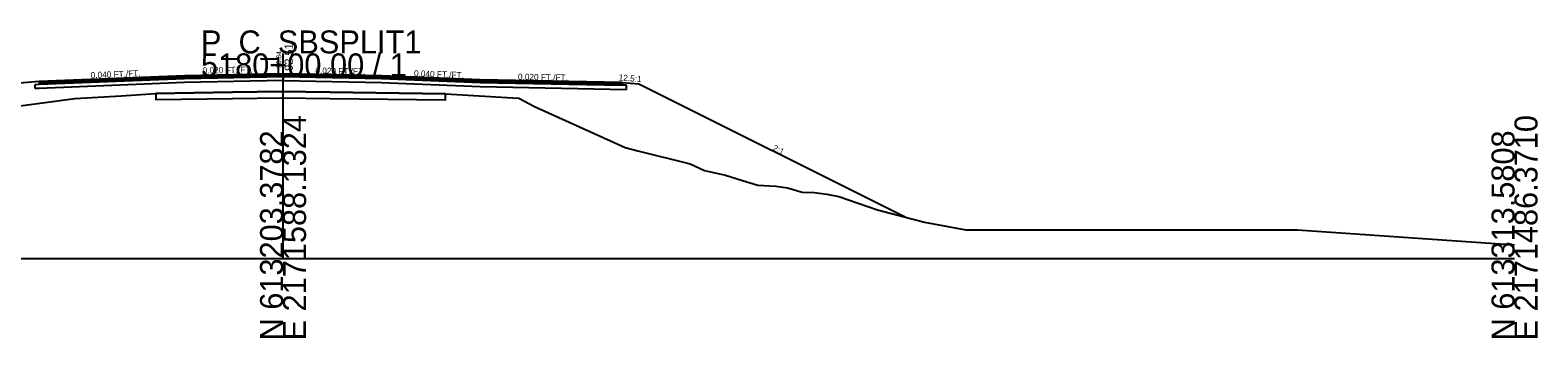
# Model space of a CAD drawing. Extents: x -26 to 1303, y -3010 to 12023.
# Drawn here: x 119.2 to 302.8, y 4490.3 to 4527.8 of the extents above; entities that cross this region are included whole.
import ezdxf

# ---------------------------------------------------------------- set-up
doc = ezdxf.new("R2010")
doc.units = 0
for name, color, linetype in [('RD_GPK_XS_Cell', 7, 'Continuous'), ('RD_XS_Base', 7, 'Continuous'), ('RD_XS_ExGround', 7, 'Continuous'), ('RD_XS_ExPaveRet', 7, 'Continuous'), ('RD_XS_Greenside', 7, 'Continuous'), ('RD_XS_Pave', 7, 'Continuous'), ('RD_XS_PaveOvlay_CP', 7, 'Continuous'), ('RD_XS_TieSlope', 7, 'Continuous'), ('RD_XS_TX_Elev_EX', 7, 'Continuous'), ('RD_XS_TX_Elev_PR', 7, 'Continuous'), ('RD_XS_TX_ShdSlope', 7, 'Continuous'), ('RD_XS_TX_Slope', 7, 'Continuous')]:
    doc.layers.add(name, color=color, linetype=linetype)

msp = doc.modelspace()

# ---------------------------------------------------------------- linework, layer by layer
at = {"layer": 'RD_GPK_XS_Cell'}
for p, q in [((150, 4500), (150, 4525)), ((0, 4500), (150, 4500)), ((150, 4500), (300, 4500))]:
    msp.add_line(p, q, dxfattribs=at)
at = {"layer": 'RD_XS_Base'}
for p, q in [((120.31, 4521.24), (138, 4521.95)), ((138, 4521.45), (120.31, 4520.74)), ((138, 4521.95), (150, 4522.19)), ((150, 4521.69), (138, 4521.45)), ((150, 4522.19), (150, 4522.35)), ((150, 4522.35), (150, 4521.69)), ((150, 4522.19), (150, 4522.19)), ((162, 4521.95), (150, 4522.19)), ((150, 4522.19), (150, 4522.19)), ((150, 4522.19), (150, 4521.69)), ((150, 4521.69), (150, 4521.69)), ((150, 4521.69), (162, 4521.45)), ((150, 4521.69), (150, 4521.69)), ((174, 4521.47), (162, 4521.95)), ((162, 4521.95), (162, 4521.95)), ((162, 4521.45), (162, 4521.45)), ((162, 4521.45), (174, 4520.97)), ((191.32, 4521.12), (174, 4521.47)), ((174, 4521.47), (174, 4521.47)), ((119.81, 4521.22), (120.31, 4521.24)), ((119.81, 4520.72), (119.81, 4521.22)), ((119.81, 4521.22), (119.81, 4521.22)), ((120.31, 4520.74), (119.81, 4520.72)), ((119.81, 4520.72), (119.81, 4520.72)), ((119.81, 4520.72), (119.81, 4520.72)), ((120.31, 4521.24), (120.31, 4521.24)), ((120.31, 4520.74), (120.31, 4520.74)), ((174, 4520.97), (174, 4520.97)), ((174, 4520.97), (191.82, 4520.61)), ((191.82, 4521.11), (191.32, 4521.12)), ((191.32, 4521.12), (191.32, 4521.12)), ((191.82, 4520.61), (191.82, 4521.11)), ((191.82, 4521.11), (191.82, 4521.11)), ((191.82, 4520.61), (191.82, 4520.61)), ((191.82, 4520.61), (191.82, 4520.61))]:
    msp.add_line(p, q, dxfattribs=at)
at = {"layer": 'RD_XS_ExGround'}
msp.add_lwpolyline([(117.03, 4518.49), (120.4, 4518.95), (123.13, 4519.31), (124.62, 4519.5), (130.28, 4519.81), (134.52, 4520.12), (143.83, 4520.26), (149.81, 4520.35), (155.71, 4520.27), (169.8, 4520.09), (178.01, 4519.6), (178.74, 4519.53), (180.62, 4518.51), (190.34, 4514.12), (191.66, 4513.51), (193.22, 4513.12), (199.6, 4511.53), (201.35, 4510.72), (203.9, 4510.14), (205.96, 4509.5), (207.85, 4508.95), (210.03, 4508.8), (211.46, 4508.6), (213.22, 4508.06), (214.68, 4508.02), (216.25, 4507.85), (217.68, 4507.57), (222.4, 4505.94), (228.13, 4504.44), (233.15, 4503.47), (241.03, 4503.47), (241.83, 4503.47), (257.46, 4503.47), (261.58, 4503.47), (265.88, 4503.47), (270.02, 4503.47), (273.58, 4503.47), (300, 4501.65)], dxfattribs=at)
at = {"layer": 'RD_XS_ExPaveRet'}
for points in [[(169.8, 4520.09), (155.71, 4520.27), (155.71, 4520.27), (149.81, 4520.35), (149.81, 4520.35), (149.81, 4520.35), (143.83, 4520.26), (143.83, 4520.26), (134.52, 4520.12), (134.52, 4519.37), (134.52, 4519.37), (143.83, 4519.51), (143.83, 4519.51), (149.81, 4519.6), (149.81, 4519.6), (149.81, 4519.6), (155.71, 4519.52), (155.71, 4519.52), (169.8, 4519.34), (169.8, 4519.34), (169.8, 4520.09), (169.8, 4520.09), (169.8, 4520.09)], [(169.8, 4520.09), (155.71, 4520.27), (149.81, 4520.35), (143.83, 4520.26), (134.52, 4520.12), (134.52, 4519.37), (143.83, 4519.51), (149.81, 4519.6), (155.71, 4519.52), (169.8, 4519.34), (169.8, 4519.34), (169.8, 4520.09), (169.8, 4520.09)]]:
    msp.add_lwpolyline(points, dxfattribs=at)
at = {"layer": 'RD_XS_Greenside'}
msp.add_line((193.32, 4521.28), (225.76, 4505.06), dxfattribs=at)
at = {"layer": 'RD_XS_Pave'}
for p, q in [((138, 4522.27), (120.31, 4521.56)), ((138, 4522.11), (120.31, 4521.4)), ((120.31, 4521.4), (138, 4522.11)), ((120.31, 4521.24), (138, 4521.95)), ((120.31, 4521.56), (120.31, 4521.56)), ((120.31, 4521.56), (120.31, 4521.4)), ((120.31, 4521.4), (120.31, 4521.4)), ((120.31, 4521.4), (120.31, 4521.24)), ((120.31, 4521.4), (120.31, 4521.4)), ((120.31, 4521.4), (120.31, 4521.4)), ((150, 4522.51), (138, 4522.27)), ((150, 4522.35), (138, 4522.11)), ((138, 4522.11), (150, 4522.35)), ((138, 4521.95), (150, 4522.19)), ((162, 4522.27), (150, 4522.51)), ((150, 4522.19), (150, 4522.35)), ((150, 4522.35), (162, 4522.11)), ((162, 4522.11), (150, 4522.35)), ((150, 4522.35), (150, 4522.35)), ((150, 4522.35), (150, 4522.19)), ((150, 4522.19), (150, 4522.19)), ((150, 4522.19), (150, 4522.19)), ((150, 4522.19), (150, 4522.19)), ((150, 4522.19), (162, 4521.95)), ((174, 4521.79), (162, 4522.27)), ((162, 4522.27), (162, 4522.27)), ((162, 4522.11), (162, 4522.11)), ((162, 4522.11), (174, 4521.63)), ((174, 4521.63), (162, 4522.11)), ((162, 4522.11), (162, 4522.11)), ((162, 4521.95), (162, 4521.95)), ((162, 4521.95), (174, 4521.47)), ((191.32, 4521.44), (174, 4521.79)), ((174, 4521.79), (174, 4521.79)), ((174, 4521.63), (174, 4521.63)), ((174, 4521.63), (191.32, 4521.28)), ((191.32, 4521.28), (174, 4521.63)), ((174, 4521.63), (174, 4521.63)), ((174, 4521.47), (174, 4521.47)), ((174, 4521.47), (191.32, 4521.12)), ((191.32, 4521.28), (191.32, 4521.44)), ((191.32, 4521.44), (191.32, 4521.44)), ((191.32, 4521.28), (191.32, 4521.28)), ((191.32, 4521.28), (191.32, 4521.28)), ((191.32, 4521.12), (191.32, 4521.28)), ((191.32, 4521.28), (191.32, 4521.28)), ((120.31, 4521.24), (120.31, 4521.24)), ((120.31, 4521.24), (120.31, 4521.24)), ((191.32, 4521.12), (191.32, 4521.12)), ((191.32, 4521.12), (191.32, 4521.12))]:
    msp.add_line(p, q, dxfattribs=at)
at = {"layer": 'RD_XS_PaveOvlay_CP'}
for p, q in [((138, 4522.27), (120.31, 4521.56)), ((120.31, 4521.56), (120.31, 4521.56)), ((150, 4522.51), (138, 4522.27)), ((162, 4522.27), (150, 4522.51)), ((174, 4521.79), (162, 4522.27)), ((162, 4522.27), (162, 4522.27)), ((191.32, 4521.44), (174, 4521.79)), ((174, 4521.79), (174, 4521.79)), ((191.32, 4521.44), (191.32, 4521.44))]:
    msp.add_line(p, q, dxfattribs=at)
at = {"layer": 'RD_XS_TieSlope'}
for p, q in [((120.31, 4521.56), (114.31, 4521.08)), ((191.32, 4521.44), (193.32, 4521.28))]:
    msp.add_line(p, q, dxfattribs=at)

# ---------------------------------------------------------------- texts
at = {"layer": 'RD_GPK_XS_Cell'}
for s, p in [('P_C_SBSPLIT1', (140, 4525)), ('5180+00.00 / 1', (140, 4522.2))]:
    msp.add_text(s, height=2.8, dxfattribs=at).set_placement(p)
for s, p in [('E 2171588.1324', (152.8, 4490)), ('E 2171486.3710', (302.8, 4490)), ('N 613203.3782', (150, 4490)), ('N 613313.5808', (300, 4490))]:
    msp.add_text(s, height=2.8, rotation=90, dxfattribs=at).set_placement(p)
at = {"layer": 'RD_XS_TX_Elev_EX'}
msp.add_text('90.34', height=0.6, rotation=90, dxfattribs=at).set_placement((149.79, 4523.21))
at = {"layer": 'RD_XS_TX_Elev_PR'}
msp.add_text('92.51', height=1, rotation=90, dxfattribs=at).set_placement((151.19, 4522.88))
at = {"layer": 'RD_XS_TX_ShdSlope'}
msp.add_text('12.5:1', height=0.75, rotation=355.4261, dxfattribs=at).set_placement((190.86, 4521.71))
at = {"layer": 'RD_XS_TX_Slope'}
for s, rotation, p in [('0.020 FT./FT.', 1.1458, (140.22, 4522.54)), ('0.020 FT./FT.', 358.8542, (153.94, 4522.53)), ('0.040 FT./FT.', 2.2906, (126.59, 4521.97)), ('0.040 FT./FT.', 357.7094, (165.94, 4522.21)), ('0.020 FT./FT.', 358.8542, (178.61, 4521.79)), ('2:1', 333.4349, (209.57, 4513.22))]:
    msp.add_text(s, height=0.75, rotation=rotation, dxfattribs=at).set_placement(p)

doc.saveas('drawing.dxf')
